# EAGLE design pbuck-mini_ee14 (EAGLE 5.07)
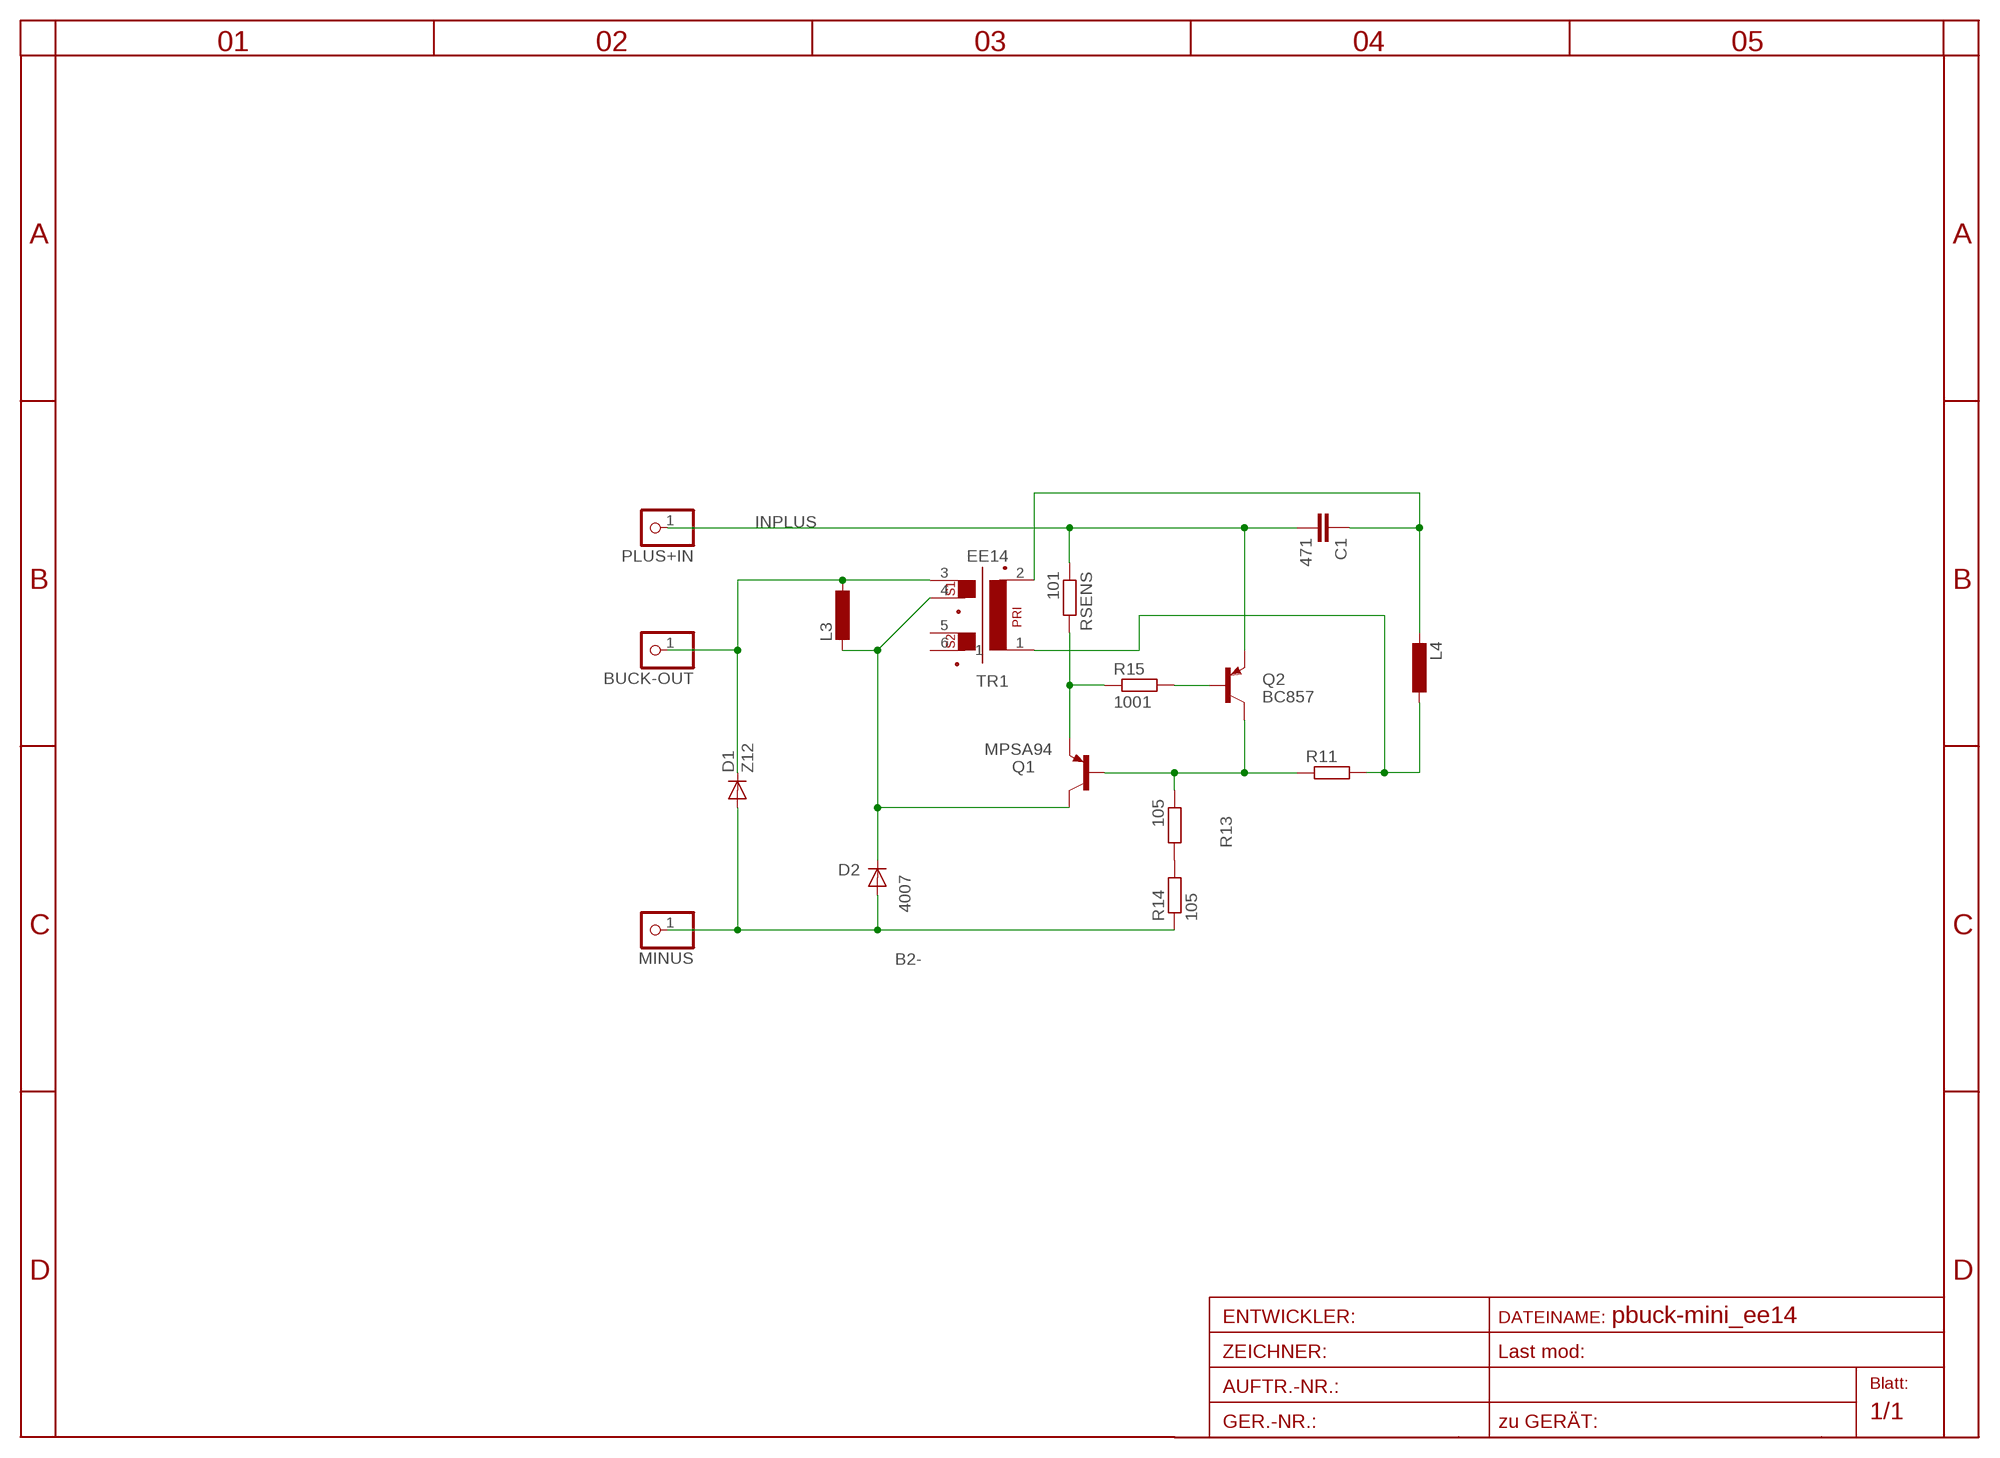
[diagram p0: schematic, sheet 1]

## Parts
BUCK-OUT  PINHD-1X11MM0  [1X1MM0]
C1  471  C-EUC0805  [C0805]
D1  Z12  DIODE-MINIMELF  [MINIMELF]
D2  4007  DIODE-SMA-DO214  [SMA-DO214AC]
L3  L-EU0204V  [0204V]
L4  L-EU0207/10  [0207/10]
MINUS  PINHD-1X11MM0  [1X1MM0]
PLUS+IN  PINHD-1X11MM0  [1X1MM0]
Q1  MPSA94  MPSW92  [TO92-CBE]
Q2  BC857  BC857ALT1SMD  [SOT23-BEC]
R11  R-EU_R0805  [R0805]
R13  105  R-EU_R1206  [R1206]
R14  105  R-EU_R1206  [R1206]
R15  1001  R-EU_R1206  [R1206]
RSENS  101  R-EU_R1206  [R1206]
TR1  EE14  EE14EE14  [EE14]

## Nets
B2-: D1.A D2.A MINUS.1 R14.1
B92: Q1.B Q2.C R11.1 R13.1
B_OUT: BUCK-OUT.1 D1.C L3.1 TR1.3
C92: D2.K(C) L3.2 Q1.C TR1.4
EB: Q1.E R15.1 RSENS.2
INPLUS: C1.2 PLUS+IN.1 Q2.E RSENS.1
L4DOT: C1.1 L4.2 TR1.2
L4NO: L4.1 R11.2 TR1.1
N$11: R13.2 R14.2
N$12: Q2.B R15.2
Unconnected: TR1.5 TR1.6

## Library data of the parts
BUCK-OUT MINUS PLUS+IN = pinhead:PINHD-1X1: PIN HEADER
C1 = rcl:C-EU: CAPACITOR, European symbol
D1 D2 = diode:DIODE-: DIODE
L3 L4 = rcl:L-EU: INDUCTOR, European symbol
Q1 = transistor-pnp:MPSW92*: PNP Transistror
Q2 = transistor-pnp:BC857*: PNP Transistror
R11 R13-R15 RSENS = rcl:R-EU_: RESISTOR, European symbol
TR1 = trafo:EE14

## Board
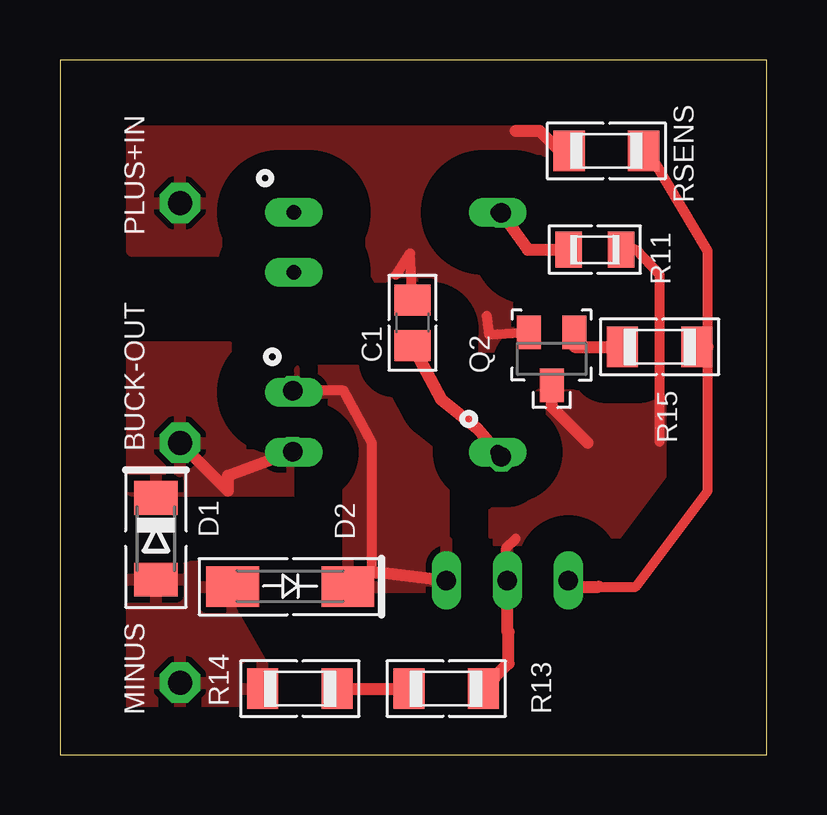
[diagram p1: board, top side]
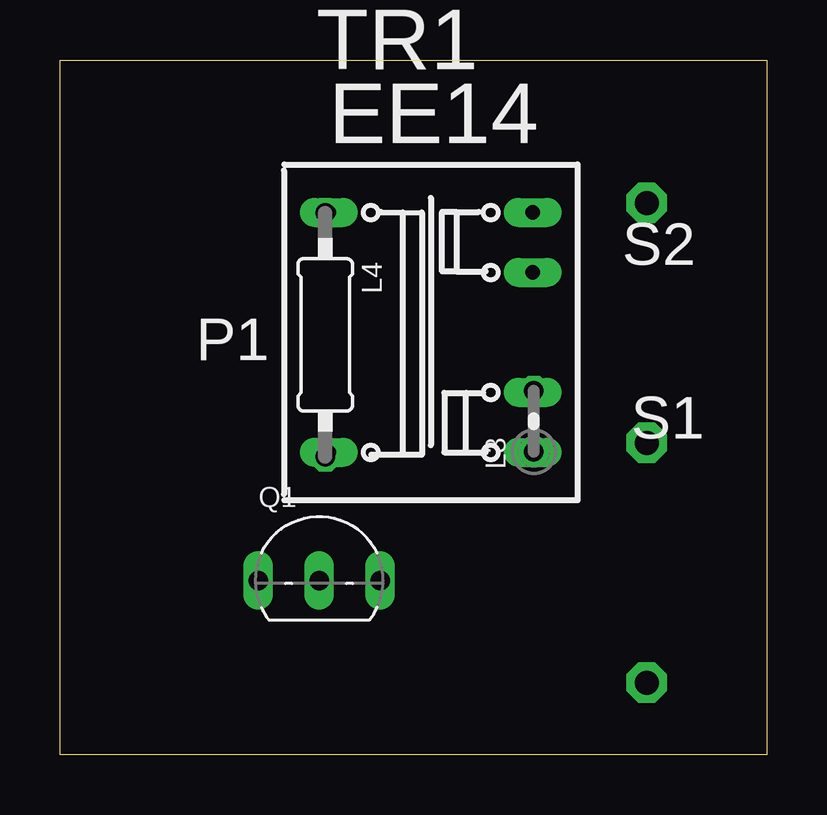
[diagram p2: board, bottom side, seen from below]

Size 29.46 x 28.96 mm. Coordinates in mm from the lower left corner, seen from the top.
Outline: 0,0 29.46,0 29.46,28.96 0,28.96 0,0
Copper layers (1*16): Top 0.035mm / dielectric 1.5mm / Bottom 0.035mm
Design rules "default *": minimum track width 10mil, minimum drill 20mil, track to track 8mil, track to pad 8mil, pad to pad 8mil, via to via 8mil, smd to smd 8mil, copper to edge 40mil, drill to drill 8mil, minimum pad ring 8mil, minimum via ring 8mil, stop-mask expansion 4mil, vias tented up to drill 0mil, thermal gap 10mil

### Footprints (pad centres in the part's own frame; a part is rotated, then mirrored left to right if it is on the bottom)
1X1MM0 = drill 1 pad 1.676 octagon: 1 0,0
C0805 = smd 1.3 x 1.5: 1 -0.95,0; 2 0.95,0
MINIMELF = smd 1.4 x 1.8: A 1.7,0; C -1.7,0
SMA-DO214AC = smd 2.2 x 1.7: A 2.4,0; K -2.4,0
0204V = drill 0.813 octagon: 1 -1.27,0; 2 1.27,0
0207/10 = drill 0.813 octagon: 1 -5.08,0; 2 5.08,0
TO92-CBE = drill 0.813 long: B 0,0; C 2.54,0; E -2.54,0
SOT23-BEC = smd 1 x 1.4: B -0.95,-1.1; C 0,1.1; E 0.95,-1.1
R0805 = smd 1.1 x 1.5: 1 -1.1,0; 2 1.1,0
R1206 = smd 1.3 x 1.7: 1 -1.55,0; 2 1.55,0
EE14 = drill 0.6 pad 1.2 long: 1 4.25,-5; 2 4.25,5; 3 -4.25,5; 4 -4.25,2.5; 5 -4.25,-2.5; 6 -4.25,-5

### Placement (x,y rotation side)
BUCK-OUT  5,13 0 top
C1  14.7,18 90 top
D1  4,9 270 top
D2  9.6,7 180 top
L3  9.7,13.9 90 bottom
L4  18.4,17.5 270 bottom
MINUS  5,3 0 top
PLUS+IN  5,23 0 top
Q1  18.65,7.26 0 bottom
Q2  20.5,16.5 180 top
R11  22.3,21.05 180 top
R13  16.1,2.75 180 top
R14  10,2.75 0 top
R15  25,17 180 top
RSENS  22.78,25.17 0 top
TR1  14,17.6 180 bottom

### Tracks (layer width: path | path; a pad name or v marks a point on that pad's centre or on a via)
B2-
  pour Top (isolate 2, rank 2): 3,8 6,8 10,1 3,1
B92
  Top 0.406: 25,13.05 25,20 24,21.05 R11.1 | 19,9 18.6,8.6 18.6,7.21 Q1.B
  Top 0.5: R13.1 18.7,3.8 18.7,5.1 18.65,5.15 Q1.B | Q2.C 20.5,14.5 22,13
  pour Top (isolate 1.5, rank 3): 20,15 23,15 24,16 26,16 27,15 27,10 25,8 19,8 18,7 17,7 17,10 18,10 20,12
B_OUT
  Top 0.406: L3.1 9.75,12.63 TR1.3
  Top 0.5: L3.1 7,11.63 7,11 BUCK-OUT.1
  pour Top (isolate 2, rank 4): 3,17 7,17 13,11 3,11
C92
  Top 0.406: L3.2 11.83,15.17 13,13 13,7.6 D2.K
  Top 0.5: 13,7.6 13.37,7.6 Q1.C
  pour Top (isolate 1.5, rank 2): 10,16 10,14 12,12 12,7 16,7 17,8 16,9 16,13 13,16
EB
  Top 0.406: RSENS.2 24.8,24.7 27,21 27,17 27,11 24,7 22.45,7
  Top 0.5: 27,17 R15.1 | 22.45,7 21.45,7 Q1.E
INPLUS
  Top 0.406: Q2.E 17.9,17.5 17.8,18.3 | C1.2 14.6,20.9 14,20
  Top 0.5: RSENS.1 21.23,24.77 20,26 19,26
  pour Top (isolate 2): 3,26 20,26 20,17 15,17 12,22 11,21 3,21
L4DOT
  Top 0.406: TR1.2 18.4,12.6 L4.2
  Top 0.5: TR1.2 17.4,13.6 15.9,14.8 C1.1
L4NO
  Top 0.406: L4.1 18.25,22.58 TR1.1
  Top 0.5: R11.2 19.5,21.05 L4.1
N$11
  Top 0.5: R14.2 R13.2
N$12
  Top 0.5: R15.2 21.45,17 Q2.B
